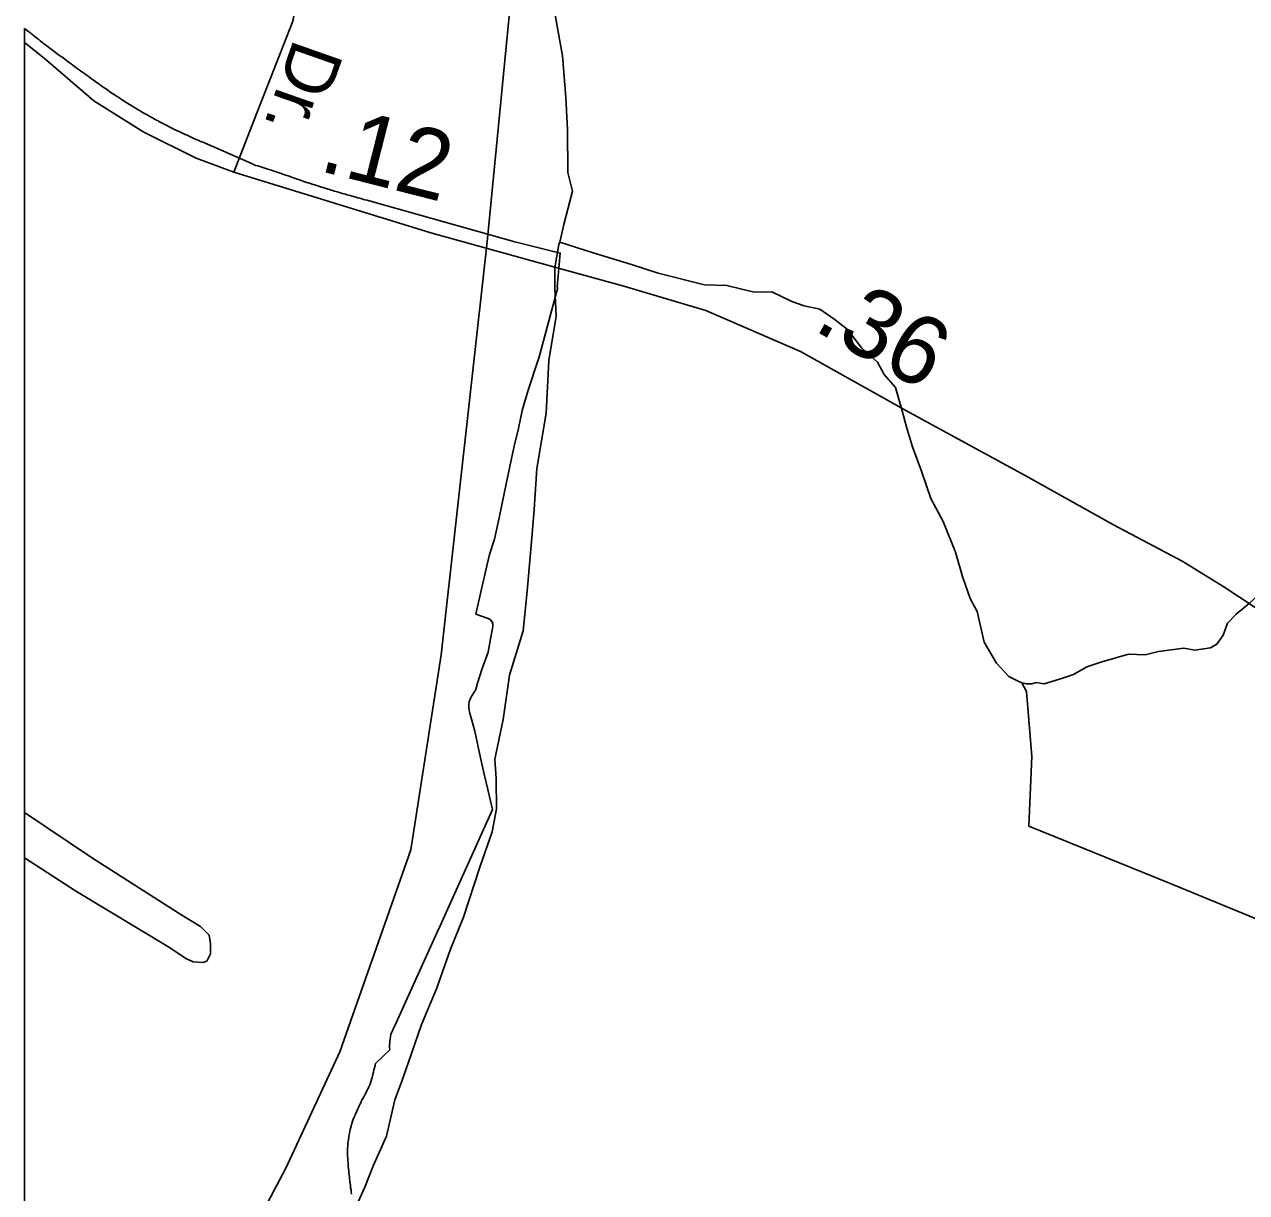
# Model space of a CAD drawing. Extents: x 2315291 to 2336543, y 597177 to 615230.
# Drawn here: x 2315744 to 2317961, y 602614 to 604731 of the extents above; entities that cross this region are included whole.
import ezdxf

# ---------------------------------------------------------------- set-up
doc = ezdxf.new("R2010")
doc.units = 0
for name, color, linetype in [('Exist Boundary Political City Limit New', 7, 'Continuous'), ('Exist Hydrographic Creek Single Shore', 7, 'Continuous'), ('Exist Hydrographic Misc Water Feature', 7, 'Continuous'), ('Exist Road Non-System Type 51', 7, 'Continuous'), ('Exist Road Secondary Mileage Hundredths English Label', 7, 'Continuous'), ('Exist Road Secondary Type 51 Attributed', 7, 'Continuous'), ('Exist Road Secondary Type 51 Label', 7, 'Continuous'), ('Map Preparation Boundary City Limit Buffer Line', 7, 'Continuous')]:
    doc.layers.add(name, color=color, linetype=linetype)

msp = doc.modelspace()

# ---------------------------------------------------------------- linework, layer by layer
at = {"layer": 'Exist Boundary Political City Limit New'}
for points in [[(2315744.5, 604723.7), (2315744.5, 597529.5), (2327185.3, 597529.5)], [(2316014.2, 604541.8), (2316010.8, 604543.6), (2316008.2, 604544.9), (2316005.2, 604546.2), (2316001.8, 604548.1), (2315999.2, 604549.4), (2315996.5, 604550.8), (2315993.2, 604552.7), (2315989.2, 604554.5), (2315986.8, 604555.9), (2315984, 604557.3), (2315980.5, 604559.2), (2315978, 604560.7), (2315975.2, 604562.2), (2315971.8, 604564.1), (2315968.2, 604566.1), (2315964.8, 604568), (2315961.2, 604570), (2315958, 604572), (2315954.5, 604574), (2315951, 604576.1), (2315948.5, 604577.6), (2315945.8, 604579.1), (2315942.5, 604581.2), (2315940, 604582.8), (2315938.2, 604583.8), (2315937.2, 604584.3), (2315934, 604586.4), (2315931.5, 604588), (2315928.8, 604589.6), (2315925.5, 604591.8), (2315923, 604593.3), (2315920.2, 604595), (2315917.5, 604596.9), (2315913.8, 604599.3), (2315911.2, 604600.9), (2315908.8, 604602.6), (2315906.2, 604604.2), (2315903.8, 604605.9), (2315901.2, 604607.6), (2315898.8, 604609.3), (2315895.5, 604611.6), (2315893, 604613.2), (2315890.5, 604615), (2315887.2, 604617.2), (2315884, 604619.6), (2315880.8, 604621.9), (2315877.5, 604624.2), (2315876.2, 604625.2), (2315874.2, 604626.6), (2315871.8, 604628.4), (2315868.8, 604630.6), (2315866.2, 604632.3), (2315863, 604634.6), (2315859.8, 604637), (2315856.5, 604639.2), (2315853.2, 604641.6), (2315850, 604644), (2315846.8, 604646.3), (2315843.5, 604648.7), (2315840.2, 604651), (2315837, 604653.3), (2315834.8, 604655.1), (2315832.2, 604656.9), (2315829.2, 604659.1), (2315825.8, 604661.6), (2315823.2, 604663.4), (2315821, 604665.2), (2315817.8, 604667.6), (2315814.5, 604670), (2315812, 604671.8), (2315809.8, 604673.5), (2315806.5, 604675.9), (2315803.2, 604678.3), (2315801, 604680.1), (2315798.5, 604681.9), (2315795.2, 604684.3), (2315793, 604686.2), (2315790.5, 604687.9), (2315788.2, 604689.8), (2315785.8, 604691.6), (2315782.5, 604694), (2315779.2, 604696.5), (2315776.2, 604698.9), (2315773, 604701.3), (2315769.8, 604703.8), (2315766.8, 604706.2), (2315763.5, 604708.7), (2315760.5, 604711.2), (2315758, 604713), (2315755.8, 604714.8), (2315752.5, 604717.3), (2315750.2, 604719.2), (2315747.8, 604721.1), (2315744.8, 604723.5), (2315744.5, 604723.7)], [(2316593.8, 603644), (2316592.5, 603648.2), (2316589, 603652.3), (2316585.5, 603654.3), (2316563.2, 603662.1), (2316574, 603710.1), (2316582, 603743.9), (2316588, 603770.2), (2316597, 603798.1), (2316605.2, 603836.7), (2316614.5, 603880.6), (2316619.8, 603906.4), (2316627, 603940.9), (2316632.8, 603966.3), (2316640.2, 603998.4), (2316644.8, 604019.1), (2316647.2, 604030.8), (2316657.8, 604068.1), (2316676, 604122.8), (2316677, 604126), (2316711.5, 604254.2), (2316710.8, 604254.4), (2316716, 604316.4), (2316633.8, 604336.8), (2316376.2, 604409.3), (2316372.8, 604410.2), (2316369.8, 604411), (2316366, 604412), (2316362, 604413.1), (2316359.2, 604413.8), (2316356.2, 604414.6), (2316352.5, 604415.7), (2316348.5, 604416.8), (2316345.8, 604417.5), (2316342.8, 604418.3), (2316339, 604419.4), (2316335, 604420.5), (2316332.2, 604421.3), (2316329.2, 604422.1), (2316326.5, 604422.9), (2316323.8, 604423.8), (2316320.8, 604424.6), (2316317.8, 604425.4), (2316315, 604426.3), (2316312, 604427.2), (2316309.2, 604428), (2316306.2, 604428.9), (2316303.5, 604429.8), (2316300.5, 604430.6), (2316297.8, 604431.5), (2316294.8, 604432.4), (2316292, 604433.2), (2316289, 604434.2), (2316286.2, 604435.1), (2316283.2, 604435.9), (2316279.5, 604437.2), (2316276.8, 604438.1), (2316274, 604439), (2316271, 604439.9), (2316268, 604440.8), (2316264.2, 604442.1), (2316261.5, 604443), (2316258.5, 604443.9), (2316254.8, 604445.2), (2316251.2, 604446.4), (2316248.2, 604447.4), (2316245.2, 604448.4), (2316241.5, 604449.7), (2316238.8, 604450.6), (2316235.8, 604451.6), (2316232, 604452.9), (2316228.5, 604454.2), (2316224.5, 604455.5), (2316220.8, 604456.9), (2316218, 604457.9), (2316215, 604458.9), (2316211.2, 604460.2), (2316208.5, 604461.2), (2316167.8, 604474.5), (2316167, 604474.7), (2316163.5, 604475.4), (2316160.8, 604476.5), (2316159.5, 604477.3), (2316066.8, 604517.8), (2316064, 604518.9), (2316059.8, 604520.8), (2316056, 604522.4), (2316053.2, 604523.6), (2316050.5, 604524.8), (2316046.8, 604526.4), (2316043.2, 604528.1), (2316039.5, 604529.8), (2316036, 604531.4), (2316032.2, 604533.1), (2316028.8, 604534.8), (2316025, 604536.5), (2316021.5, 604538.2), (2316018, 604540), (2316014.2, 604541.8)], [(2316336.8, 602618.4), (2316336, 602622.4), (2316335.8, 602626.2), (2316334.8, 602634.2), (2316334.2, 602638.5), (2316334, 602641.4), (2316333.2, 602645.9), (2316333, 602649.9), (2316332.5, 602653.9), (2316332.2, 602657.4), (2316331.8, 602660.8), (2316331.5, 602663.8), (2316331.5, 602666.8), (2316331, 602671.8), (2316330.8, 602675.2), (2316330.5, 602679.8), (2316330.5, 602682.8), (2316330.2, 602685.8), (2316330.2, 602693.9), (2316330.8, 602697.8), (2316331.2, 602702.5), (2316331.8, 602706.3), (2316332, 602709.2), (2316333, 602714.4), (2316333.5, 602718.4), (2316334, 602721.4), (2316334.8, 602725.2), (2316335.2, 602728.2), (2316336.8, 602734), (2316337.5, 602736.8), (2316338.8, 602740.6), (2316340, 602744.9), (2316341.2, 602747.8), (2316342.8, 602750.7), (2316343.8, 602753.4), (2316345.2, 602757), (2316347, 602760.9), (2316348.5, 602764.4), (2316350.2, 602767.8), (2316351.5, 602770.7), (2316353.2, 602774.7), (2316354.8, 602777.7), (2316356, 602780.3), (2316358, 602783.9), (2316359.8, 602787.3), (2316362.2, 602791.9), (2316364.5, 602796.2), (2316366.2, 602799.8), (2316367.5, 602802.4), (2316369, 602805.1), (2316371.2, 602810.3), (2316372.8, 602814.5), (2316373.8, 602818.3), (2316374.8, 602822.2), (2316376.2, 602827.8), (2316377.2, 602831.8), (2316378.2, 602835.8), (2316379.2, 602839.6), (2316380.5, 602844), (2316381, 602847.4), (2316406.8, 602872.1), (2316406.5, 602877), (2316406.5, 602881.2), (2316406.8, 602885.2), (2316407.2, 602888.7), (2316407.8, 602892.2), (2316408.5, 602896.1), (2316409, 602901), (2316411.8, 602906.7), (2316414, 602911.8), (2316415.8, 602914.8), (2316493.2, 603085.8), (2316498.2, 603097.1), (2316533, 603174), (2316533.5, 603174.7), (2316561.2, 603236.8), (2316563.8, 603242.2), (2316593.2, 603308.2), (2316584.8, 603343.9), (2316578, 603371.9), (2316571.5, 603401.6), (2316561, 603449.6), (2316552.2, 603482.8), (2316551, 603487.5), (2316550.2, 603493.5), (2316550.2, 603498.1), (2316551.2, 603503.1), (2316552.8, 603507.6), (2316554.2, 603511.2), (2316562.8, 603525.1), (2316566.2, 603537.1), (2316573.8, 603561.7), (2316585.5, 603593.1), (2316589.5, 603617.4), (2316593.2, 603636.2), (2316594, 603639.8), (2316593.8, 603644)], [(2316337.5, 602610.5), (2316337.2, 602614.4), (2316336.8, 602618.4)]]:
    msp.add_lwpolyline(points, dxfattribs=at)
at = {"layer": 'Exist Hydrographic Creek Single Shore'}
msp.add_lwpolyline([(2315744.5, 602054.5), (2315989.3, 602291.1), (2316112.3, 602456.9), (2316218.3, 602658.1), (2316316.3, 602868.8), (2316445.3, 603235), (2316500.2, 603588.3), (2316583.3, 604336.6), (2316666.1, 605186.6), (2316690.1, 605279.5), (2316697.3, 605388), (2316981.3, 606075.5), (2317204.2, 606258.5), (2317425.2, 606522.7)], dxfattribs=at)
at = {"layer": 'Exist Hydrographic Misc Water Feature'}
for points in [[(2316770.7, 605314.2), (2316759.4, 605264), (2316755.7, 605214.2), (2316748.4, 605162.2), (2316744.5, 605136.1), (2316755.5, 605071.9), (2316753.7, 605038.2), (2316752.1, 605005.9), (2316750.6, 604956.3), (2316745.3, 604906), (2316734, 604855.8), (2316718.4, 604803.8), (2316704.7, 604761.6), (2316719.9, 604673.8), (2316726.4, 604598.2), (2316729.5, 604540.1), (2316730.1, 604462.2), (2316738.5, 604428.5), (2316722.9, 604367.9), (2316715.6, 604336.2)], [(2316715.6, 604336.2), (2316713.5, 604332.1), (2316706.1, 604289.8), (2316706.1, 604252.1), (2316709, 604202.2), (2316695.5, 604121.9), (2316690.7, 604026.1), (2316673.5, 603926.1), (2316668.8, 603851.7), (2316664.9, 603807.7), (2316656.1, 603703.6), (2316648.9, 603631.7), (2316624.1, 603551.5), (2316612.8, 603471.3), (2316597.4, 603399.4), (2316599.9, 603363.3), (2316600.3, 603309.3), (2316592.9, 603267.4), (2316570, 603203.2), (2316540.8, 603112.7), (2316517.1, 603054.6), (2316491.8, 602982.6), (2316464.6, 602918.1), (2316445.5, 602863.8), (2316428.1, 602813.7), (2316416, 602781.9), (2316401.2, 602715.6), (2316377.6, 602663.2), (2316362, 602623.3), (2316335, 602565)], [(2317553.2, 603537.3), (2317545.4, 603541.4), (2317529.4, 603549.1), (2317507.5, 603573.1), (2317484.7, 603610.9), (2317472.4, 603666.7), (2317459.7, 603690.5), (2317445.5, 603730.4), (2317432.8, 603774.1), (2317410.3, 603829.8), (2317387.9, 603871.7), (2317371.5, 603921.2), (2317354.9, 603965), (2317344.4, 603999.1), (2317336.2, 604030.7), (2317323.9, 604072.7), (2317303.8, 604096.4), (2317291.7, 604118.5), (2317263.2, 604143.9), (2317237, 604177.9), (2317214.9, 604195.4), (2317186.6, 604215), (2317158.3, 604220.9), (2317136.1, 604228.7), (2317100, 604246.3), (2317068, 604245.8), (2317018.2, 604257.4), (2316978, 604259), (2316893.9, 604280.2), (2316845.6, 604295.6), (2316775.6, 604316.6), (2316715.6, 604336.2)], [(2318003.3, 603720.2), (2317983.4, 603698.1), (2317965.8, 603681.7), (2317942, 603661.7), (2317926.2, 603645.5), (2317918.2, 603623.6), (2317906.7, 603607.5), (2317895, 603601.1), (2317866.7, 603596.8), (2317846.8, 603600.6), (2317800.7, 603594.2), (2317776.7, 603588.1), (2317746.8, 603589.3), (2317696.7, 603575), (2317671.3, 603566.7), (2317647.1, 603552.4), (2317621.5, 603544.1), (2317593.4, 603535.8), (2317579.2, 603537.9), (2317571.2, 603535.8), (2317561.6, 603535.7), (2317553.2, 603537.3)], [(2319290, 602840.4), (2319251.8, 602852.2), (2319217.8, 602861.8), (2319163.5, 602895.2), (2319109.3, 602912.6), (2319057.2, 602924.1), (2319019.1, 602939.6), (2318981, 602953), (2318938.7, 602962.6), (2318895.1, 602970), (2318871.1, 602974.1), (2318856.9, 602975.7), (2318834.8, 602973.8), (2318547.3, 602956.7), (2318381.4, 602940.7), (2318208.7, 603014.9), (2317821, 603174.6), (2317566.1, 603277.9), (2317571, 603403.7), (2317561.6, 603521.5), (2317553.2, 603537.3)]]:
    msp.add_lwpolyline(points, dxfattribs=at)
at = {"layer": 'Exist Road Non-System Type 51'}
msp.add_lwpolyline([(2315744.5, 603302.3), (2315868, 603219.9), (2316030.1, 603116.3), (2316063.9, 603096), (2316079.6, 603080.2), (2316081.9, 603064.5), (2316081.9, 603055.4), (2316081.9, 603046.4), (2316075.1, 603032.9), (2316068.4, 603030.7), (2316050.3, 603032), (2316037.2, 603037.7), (2316007.6, 603057.7), (2315838.8, 603159.1), (2315744.5, 603220.3)], dxfattribs=at)
at = {"layer": 'Exist Road Secondary Type 51 Attributed'}
for points in [[(2316124.3, 604463.3), (2316161.3, 604557.8), (2316231.3, 604736.5), (2316237.1, 604766.5), (2316236.8, 604788.5), (2316228, 604846.4), (2316218.4, 605039.4), (2316198.2, 605269.7), (2316181.6, 605363.6), (2316168.7, 605437.3), (2316141.1, 605492.6)], [(2315744.5, 604698.1), (2315780.2, 604669.9), (2315870.4, 604592.6), (2315960.7, 604535.4), (2316056.1, 604488.7), (2316124.3, 604463.3)], [(2316124.3, 604463.3), (2316481.2, 604353.3), (2316703.8, 604291.7), (2316831.6, 604256.4), (2316980.2, 604212.6), (2317151.6, 604138.2), (2317349.7, 604027.7), (2317559.2, 603913.3), (2317719.2, 603823.8), (2317844.9, 603757.1), (2317919.2, 603711.3), (2317974.4, 603675.1), (2318010.6, 603646.5), (2318050.6, 603612.2), (2318092.5, 603572.2), (2318132.5, 603530.3), (2318166.8, 603482.6), (2318199.2, 603433.1), (2318241.1, 603369.2), (2318271.6, 603310.1), (2318290.6, 603260.6)]]:
    msp.add_lwpolyline(points, dxfattribs=at)
at = {"layer": 'Map Preparation Boundary City Limit Buffer Line'}
for points in [[(2315744.5, 604723.7), (2315744.5, 597529.5), (2327185.3, 597529.5)], [(2316014.2, 604541.8), (2316010.8, 604543.6), (2316008.2, 604544.9), (2316005.2, 604546.2), (2316001.8, 604548.1), (2315999.2, 604549.4), (2315996.5, 604550.8), (2315993.2, 604552.7), (2315989.2, 604554.5), (2315986.8, 604555.9), (2315984, 604557.3), (2315980.5, 604559.2), (2315978, 604560.7), (2315975.2, 604562.2), (2315971.8, 604564.1), (2315968.2, 604566.1), (2315964.8, 604568), (2315961.2, 604570), (2315958, 604572), (2315954.5, 604574), (2315951, 604576.1), (2315948.5, 604577.6), (2315945.8, 604579.1), (2315942.5, 604581.2), (2315940, 604582.8), (2315938.2, 604583.8), (2315937.2, 604584.3), (2315934, 604586.4), (2315931.5, 604588), (2315928.8, 604589.6), (2315925.5, 604591.8), (2315923, 604593.3), (2315920.2, 604595), (2315917.5, 604596.9), (2315913.8, 604599.3), (2315911.2, 604600.9), (2315908.8, 604602.6), (2315906.2, 604604.2), (2315903.8, 604605.9), (2315901.2, 604607.6), (2315898.8, 604609.3), (2315895.5, 604611.6), (2315893, 604613.2), (2315890.5, 604615), (2315887.2, 604617.2), (2315884, 604619.6), (2315880.8, 604621.9), (2315877.5, 604624.2), (2315876.2, 604625.2), (2315874.2, 604626.6), (2315871.8, 604628.4), (2315868.8, 604630.6), (2315866.2, 604632.3), (2315863, 604634.6), (2315859.8, 604637), (2315856.5, 604639.2), (2315853.2, 604641.6), (2315850, 604644), (2315846.8, 604646.3), (2315843.5, 604648.7), (2315840.2, 604651), (2315837, 604653.3), (2315834.8, 604655.1), (2315832.2, 604656.9), (2315829.2, 604659.1), (2315825.8, 604661.6), (2315823.2, 604663.4), (2315821, 604665.2), (2315817.8, 604667.6), (2315814.5, 604670), (2315812, 604671.8), (2315809.8, 604673.5), (2315806.5, 604675.9), (2315803.2, 604678.3), (2315801, 604680.1), (2315798.5, 604681.9), (2315795.2, 604684.3), (2315793, 604686.2), (2315790.5, 604687.9), (2315788.2, 604689.8), (2315785.8, 604691.6), (2315782.5, 604694), (2315779.2, 604696.5), (2315776.2, 604698.9), (2315773, 604701.3), (2315769.8, 604703.8), (2315766.8, 604706.2), (2315763.5, 604708.7), (2315760.5, 604711.2), (2315758, 604713), (2315755.8, 604714.8), (2315752.5, 604717.3), (2315750.2, 604719.2), (2315747.8, 604721.1), (2315744.8, 604723.5), (2315744.5, 604723.7)], [(2316593.8, 603644), (2316592.5, 603648.2), (2316589, 603652.3), (2316585.5, 603654.3), (2316563.2, 603662.1), (2316574, 603710.1), (2316582, 603743.9), (2316588, 603770.2), (2316597, 603798.1), (2316605.2, 603836.7), (2316614.5, 603880.6), (2316619.8, 603906.4), (2316627, 603940.9), (2316632.8, 603966.3), (2316640.2, 603998.4), (2316644.8, 604019.1), (2316647.2, 604030.8), (2316657.8, 604068.1), (2316676, 604122.8), (2316677, 604126), (2316711.5, 604254.2), (2316710.8, 604254.4), (2316716, 604316.4), (2316633.8, 604336.8), (2316376.2, 604409.3), (2316372.8, 604410.2), (2316369.8, 604411), (2316366, 604412), (2316362, 604413.1), (2316359.2, 604413.8), (2316356.2, 604414.6), (2316352.5, 604415.7), (2316348.5, 604416.8), (2316345.8, 604417.5), (2316342.8, 604418.3), (2316339, 604419.4), (2316335, 604420.5), (2316332.2, 604421.3), (2316329.2, 604422.1), (2316326.5, 604422.9), (2316323.8, 604423.8), (2316320.8, 604424.6), (2316317.8, 604425.4), (2316315, 604426.3), (2316312, 604427.2), (2316309.2, 604428), (2316306.2, 604428.9), (2316303.5, 604429.8), (2316300.5, 604430.6), (2316297.8, 604431.5), (2316294.8, 604432.4), (2316292, 604433.2), (2316289, 604434.2), (2316286.2, 604435.1), (2316283.2, 604435.9), (2316279.5, 604437.2), (2316276.8, 604438.1), (2316274, 604439), (2316271, 604439.9), (2316268, 604440.8), (2316264.2, 604442.1), (2316261.5, 604443), (2316258.5, 604443.9), (2316254.8, 604445.2), (2316251.2, 604446.4), (2316248.2, 604447.4), (2316245.2, 604448.4), (2316241.5, 604449.7), (2316238.8, 604450.6), (2316235.8, 604451.6), (2316232, 604452.9), (2316228.5, 604454.2), (2316224.5, 604455.5), (2316220.8, 604456.9), (2316218, 604457.9), (2316215, 604458.9), (2316211.2, 604460.2), (2316208.5, 604461.2), (2316167.8, 604474.5), (2316167, 604474.7), (2316163.5, 604475.4), (2316160.8, 604476.5), (2316159.5, 604477.3), (2316066.8, 604517.8), (2316064, 604518.9), (2316059.8, 604520.8), (2316056, 604522.4), (2316053.2, 604523.6), (2316050.5, 604524.8), (2316046.8, 604526.4), (2316043.2, 604528.1), (2316039.5, 604529.8), (2316036, 604531.4), (2316032.2, 604533.1), (2316028.8, 604534.8), (2316025, 604536.5), (2316021.5, 604538.2), (2316018, 604540), (2316014.2, 604541.8)], [(2316336.8, 602618.4), (2316336, 602622.4), (2316335.8, 602626.2), (2316334.8, 602634.2), (2316334.2, 602638.5), (2316334, 602641.4), (2316333.2, 602645.9), (2316333, 602649.9), (2316332.5, 602653.9), (2316332.2, 602657.4), (2316331.8, 602660.8), (2316331.5, 602663.8), (2316331.5, 602666.8), (2316331, 602671.8), (2316330.8, 602675.2), (2316330.5, 602679.8), (2316330.5, 602682.8), (2316330.2, 602685.8), (2316330.2, 602693.9), (2316330.8, 602697.8), (2316331.2, 602702.5), (2316331.8, 602706.3), (2316332, 602709.2), (2316333, 602714.4), (2316333.5, 602718.4), (2316334, 602721.4), (2316334.8, 602725.2), (2316335.2, 602728.2), (2316336.8, 602734), (2316337.5, 602736.8), (2316338.8, 602740.6), (2316340, 602744.9), (2316341.2, 602747.8), (2316342.8, 602750.7), (2316343.8, 602753.4), (2316345.2, 602757), (2316347, 602760.9), (2316348.5, 602764.4), (2316350.2, 602767.8), (2316351.5, 602770.7), (2316353.2, 602774.7), (2316354.8, 602777.7), (2316356, 602780.3), (2316358, 602783.9), (2316359.8, 602787.3), (2316362.2, 602791.9), (2316364.5, 602796.2), (2316366.2, 602799.8), (2316367.5, 602802.4), (2316369, 602805.1), (2316371.2, 602810.3), (2316372.8, 602814.5), (2316373.8, 602818.3), (2316374.8, 602822.2), (2316376.2, 602827.8), (2316377.2, 602831.8), (2316378.2, 602835.8), (2316379.2, 602839.6), (2316380.5, 602844), (2316381, 602847.4), (2316406.8, 602872.1), (2316406.5, 602877), (2316406.5, 602881.2), (2316406.8, 602885.2), (2316407.2, 602888.7), (2316407.8, 602892.2), (2316408.5, 602896.1), (2316409, 602901), (2316411.8, 602906.7), (2316414, 602911.8), (2316415.8, 602914.8), (2316493.2, 603085.8), (2316498.2, 603097.1), (2316533, 603174), (2316533.5, 603174.7), (2316561.2, 603236.8), (2316563.8, 603242.2), (2316593.2, 603308.2), (2316584.8, 603343.9), (2316578, 603371.9), (2316571.5, 603401.6), (2316561, 603449.6), (2316552.2, 603482.8), (2316551, 603487.5), (2316550.2, 603493.5), (2316550.2, 603498.1), (2316551.2, 603503.1), (2316552.8, 603507.6), (2316554.2, 603511.2), (2316562.8, 603525.1), (2316566.2, 603537.1), (2316573.8, 603561.7), (2316585.5, 603593.1), (2316589.5, 603617.4), (2316593.2, 603636.2), (2316594, 603639.8), (2316593.8, 603644)], [(2316337.5, 602610.5), (2316337.2, 602614.4), (2316336.8, 602618.4)]]:
    msp.add_lwpolyline(points, dxfattribs=at)

# ---------------------------------------------------------------- texts
at = {"layer": 'Exist Road Secondary Mileage Hundredths English Label'}
for s, rotation, p in [('.12', 345.7579, (2316275.8, 604466.1)), ('.36', 330.8365, (2317172.5, 604178.4))]:
    msp.add_text(s, height=125, rotation=rotation, dxfattribs=at).set_placement(p)
at = {"layer": 'Exist Road Secondary Type 51 Label'}
msp.add_text('Dr.', height=95, rotation=250.6196, dxfattribs=at).set_placement((2316234.1, 604707.6))

doc.saveas('drawing.dxf')
